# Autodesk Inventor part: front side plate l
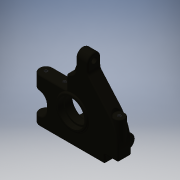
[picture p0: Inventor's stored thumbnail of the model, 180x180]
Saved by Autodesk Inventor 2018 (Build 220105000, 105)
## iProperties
Shininess: 41.0
Compacted: True
Length Units: 11272
Angle Units: 11279
Time Units: 11290
Mass Units: 11286
Length Display Precision: 3
Angle Display Precision: 2
Company: Autodesk
Created: 2001-02
Part Number: front side plate l
Document SubType Name: Modeling
Designer: Autodesk, Inc.
Material: Stiffzel
Project: Inventor Samples
Density: 1.28 g/cm^3
Stock Number: front side plate l
Mass: 15.7207 g
Surface Area: 55.8097 cm^2
Volume: 12.2818 cm^3
Appearance: Stiffzel
Density: 0.0
Volumn: 0.0
Area: 0.0
PropertySet Name: Model Information
Control State: 0
Master: False
Checked Out: False
Author: Autodesk, Inc.
Revision Number: A
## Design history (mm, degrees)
node "front side plate r" dims "d3" = 10
body "Solid1"
tag "TaggingFeature2"
feature "DerivedBody::front side plate r" dims "d3" = 10
